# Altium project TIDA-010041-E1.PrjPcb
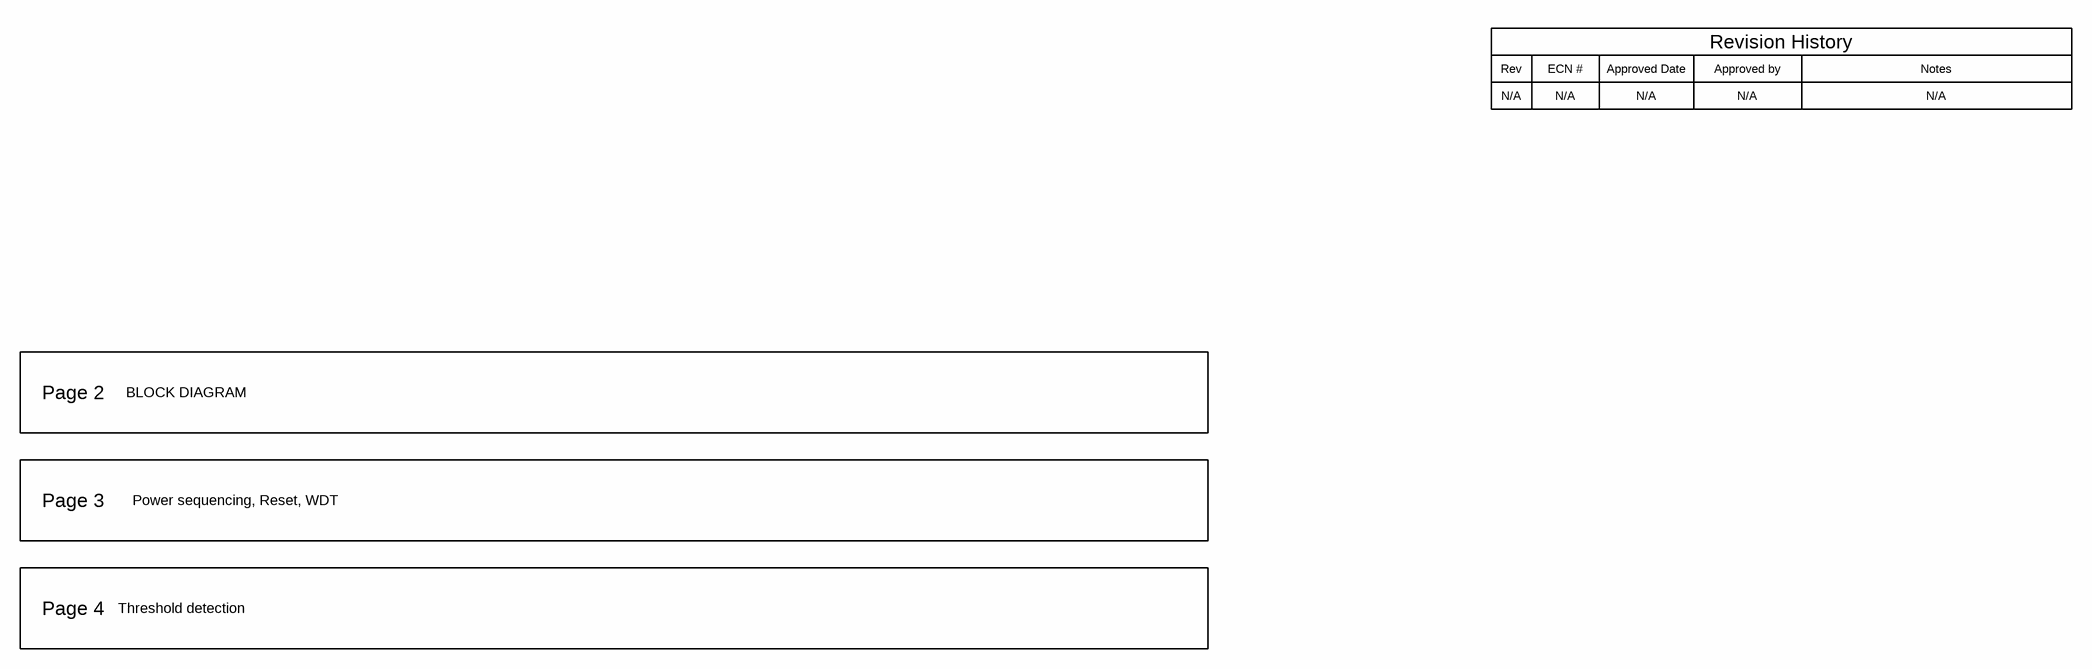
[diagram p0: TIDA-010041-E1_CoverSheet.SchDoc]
CopyrightYear: 2018; PCB_Layout: Avinash N; PCB_Rev: E1; PRJ_Customer: Public Release; PRJ_Engineer: Harsh Misra; PRJ_Number: TIDA-010041; PRJ_Title: TIDA-010041; SCH_Rev: E1; TechSupport: http://www.ti.com/support; TID: 010041
5 sheets, 147 parts. Net scope: flat (ports and power ports of the same name join across sheets).
Board file: TIDA-010041-E1.PcbDoc
Sheets:
  TIDA-010041-E1_CoverSheet.SchDoc
  TIDA-010041-E1_Block Diagram.SchDoc
  TIDA-010041-E1_Power sequencing, Reset, WDT.SchDoc
  TIDA-010041-E1_Threshold detection.SchDoc
  TIDA-010041-E1_EVM_Hardware.SchDoc

## Sheet TIDA-010041-E1_CoverSheet.SchDoc
size 431 x 279 mm; Date: Not shown in title block; ApprovedBy: Not shown in title block; CheckedBy: Not shown in title block; Author: Not shown in title block; CompanyName: Not shown in title block; Engineer: Not shown in title block; Organization: Not shown in title block; Address1: Not shown in title block; Address2: Not shown in title block; Address3: Not shown in title block; Address4: Not shown in title block; DocumentNumber: 1; Revision: Use project parameter SCH_Rev; SheetNumber: 1; SheetTotal: 5; PageSetup: Record=PageOptions¦CenterHorizontal=True¦CenterVertical=True¦PrintScale=1.00¦XCorrection=1.00¦YCorrection=1.00¦PrintKind=0¦BorderSize=5000000¦LeftOffset=0¦BottomOffset=0¦Orientation=2¦PaperLength=1000¦PaperWidth=1000¦Scale=100¦PaperSource=15¦PrintQuality=600¦MediaType=1¦DitherType=10¦PaperKind=Letter¦PrintScaleMode=1

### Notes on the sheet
- Rev
- N/A
- ECN #
- Approved Date
- Approved by
- Revision History
- Notes
- Page 2
- BLOCK DIAGRAM
- Page 3
- Power sequencing, Reset, WDT
- Page 4
- Threshold detection

## Sheet TIDA-010041-E1_Block Diagram.SchDoc
size 431 x 279 mm; Date: Not shown in title block; ApprovedBy: Not shown in title block; CheckedBy: Not shown in title block; Author: Not shown in title block; CompanyName: Not shown in title block; Engineer: Not shown in title block; Organization: Not shown in title block; Address1: Not shown in title block; Address2: Not shown in title block; Address3: Not shown in title block; Address4: Not shown in title block; DocumentNumber: 1; Revision: Use project parameter SCH_Rev; SheetNumber: 2; SheetTotal: 5; PageSetup: Record=PageOptions¦CenterHorizontal=True¦CenterVertical=True¦PrintScale=1.00¦XCorrection=1.00¦YCorrection=1.00¦PrintKind=0¦BorderSize=5000000¦LeftOffset=0¦BottomOffset=0¦Orientation=2¦PaperLength=1000¦PaperWidth=1000¦Scale=100¦PaperSource=15¦PrintQuality=600¦MediaType=1¦DitherType=10¦PaperKind=Letter¦PrintScaleMode=1
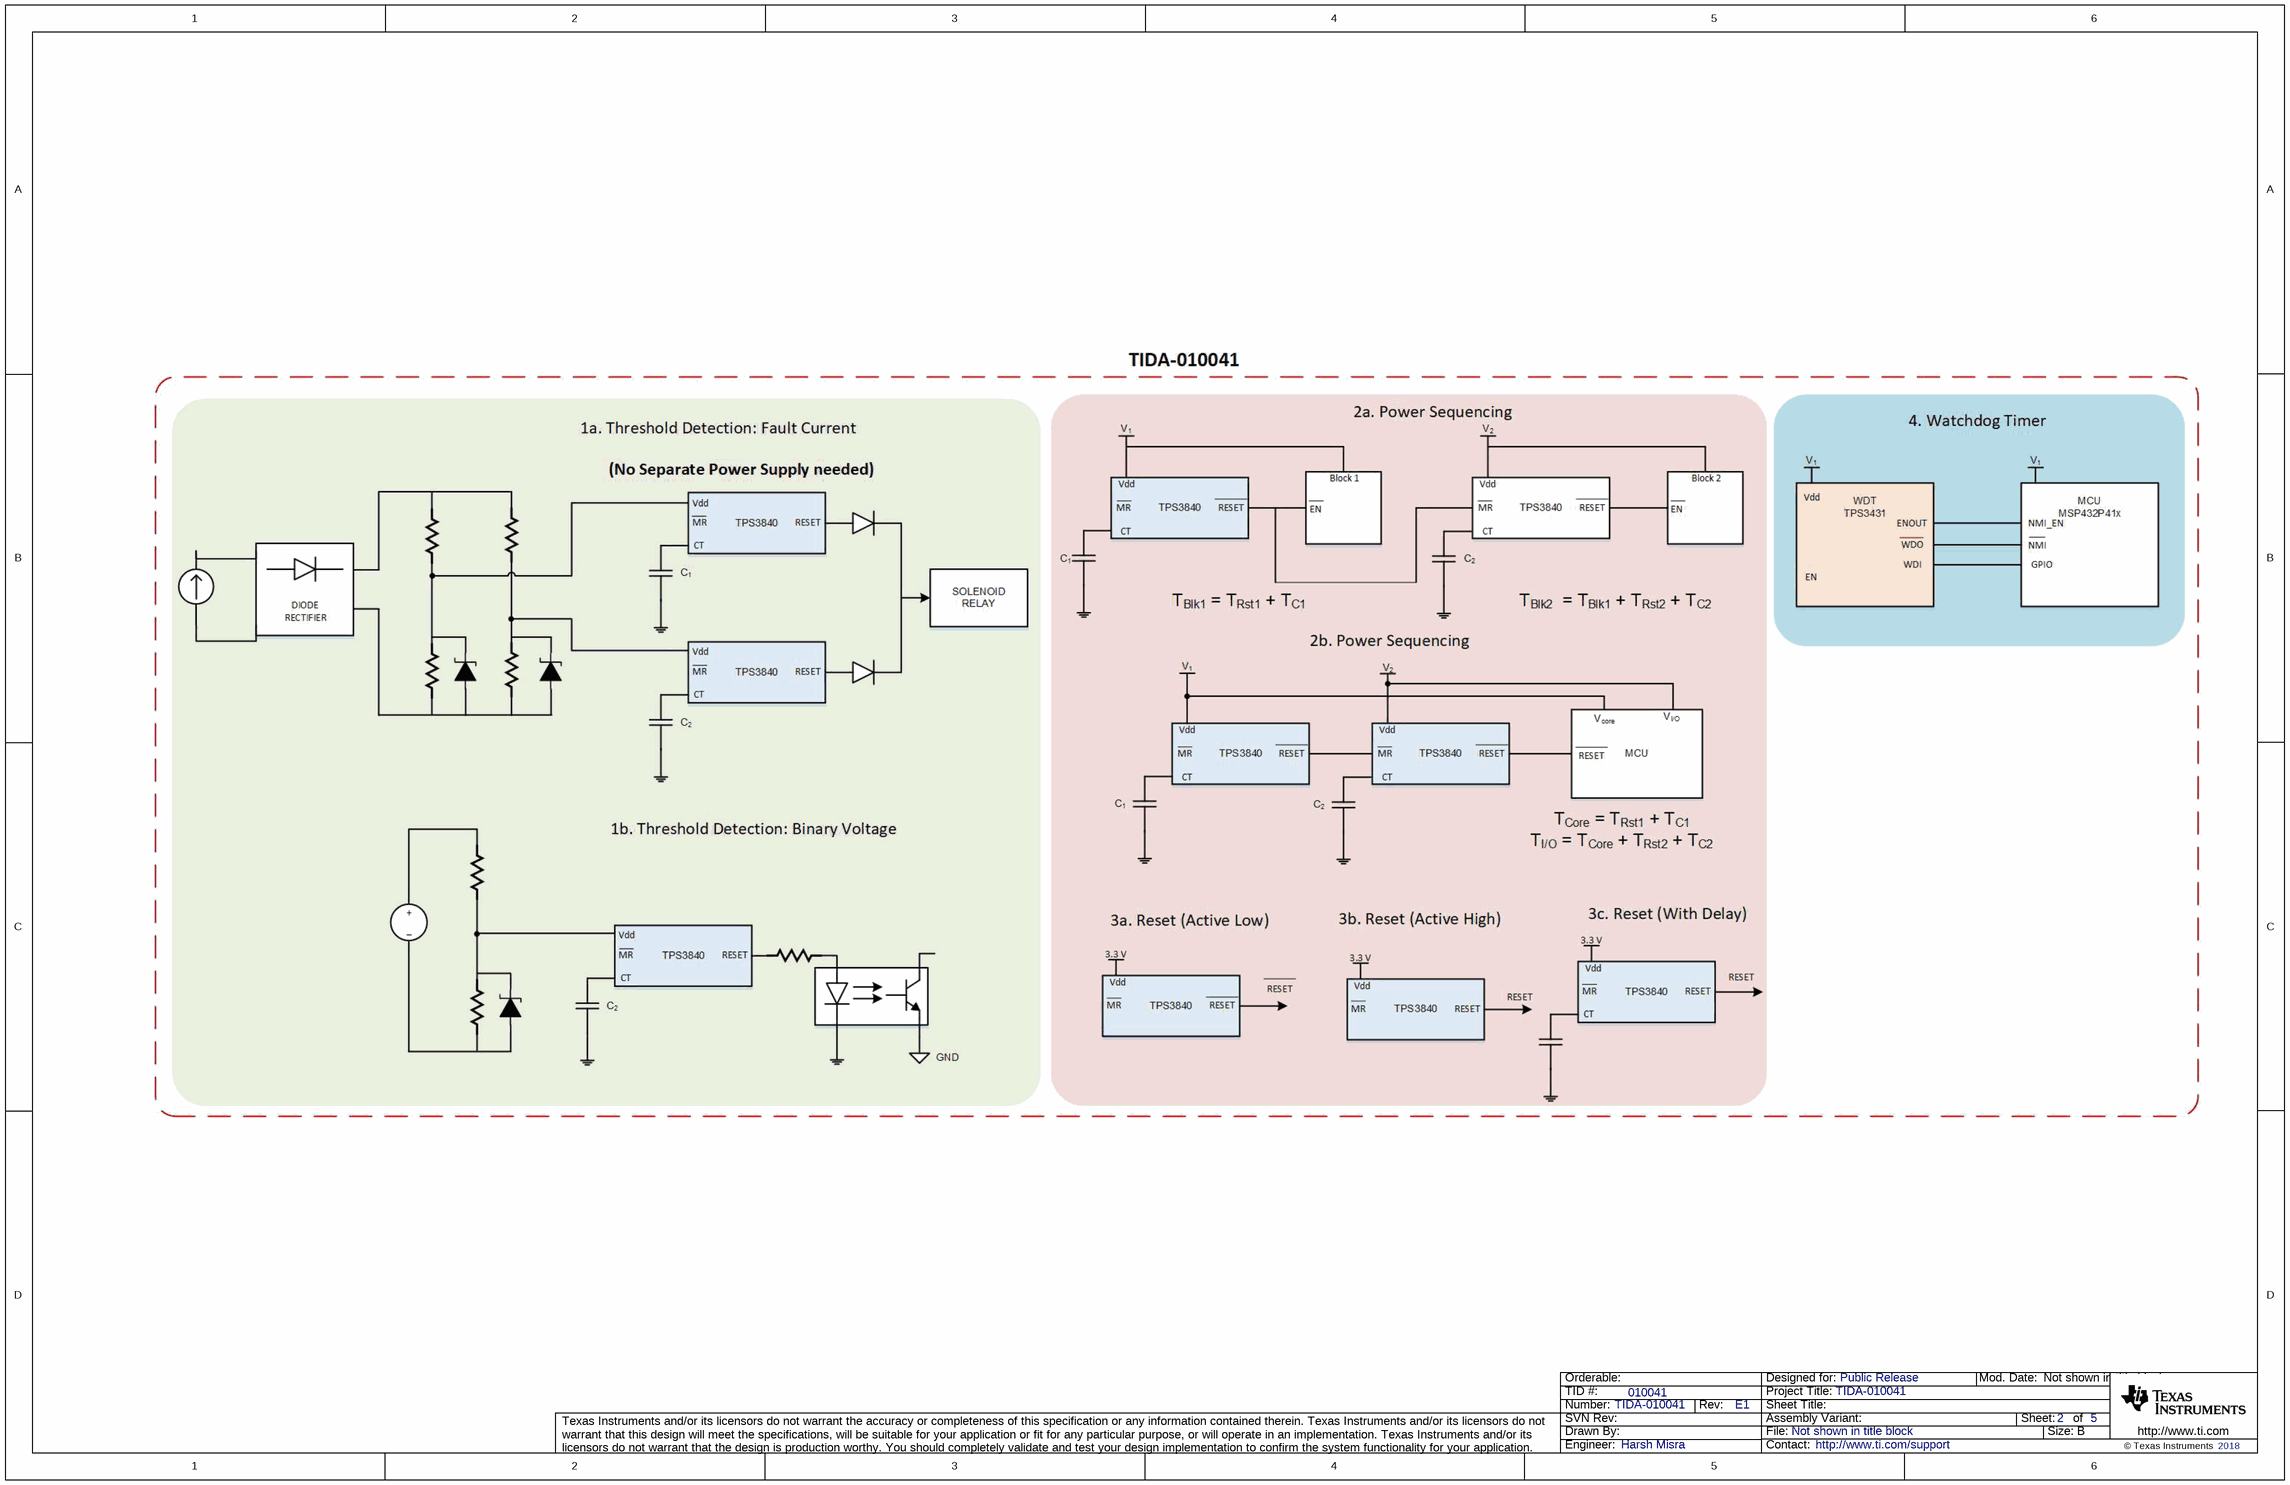
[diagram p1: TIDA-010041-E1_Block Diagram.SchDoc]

## Sheet TIDA-010041-E1_Power sequencing, Reset, WDT.SchDoc
size 431 x 279 mm; Date: Not shown in title block; ApprovedBy: Not shown in title block; CheckedBy: Not shown in title block; Author: Not shown in title block; CompanyName: Not shown in title block; Engineer: Not shown in title block; Organization: Not shown in title block; Address1: Not shown in title block; Address2: Not shown in title block; Address3: Not shown in title block; Address4: Not shown in title block; DocumentNumber: 1; Revision: Use project parameter SCH_Rev; SheetNumber: 3; SheetTotal: 5; PageSetup: Record=PageOptions¦CenterHorizontal=True¦CenterVertical=True¦PrintScale=1.00¦XCorrection=1.00¦YCorrection=1.00¦PrintKind=0¦BorderSize=5000000¦LeftOffset=0¦BottomOffset=0¦Orientation=2¦PaperLength=1000¦PaperWidth=1000¦Scale=100¦PaperSource=15¦PrintQuality=600¦MediaType=1¦DitherType=10¦PaperKind=Letter¦PrintScaleMode=1
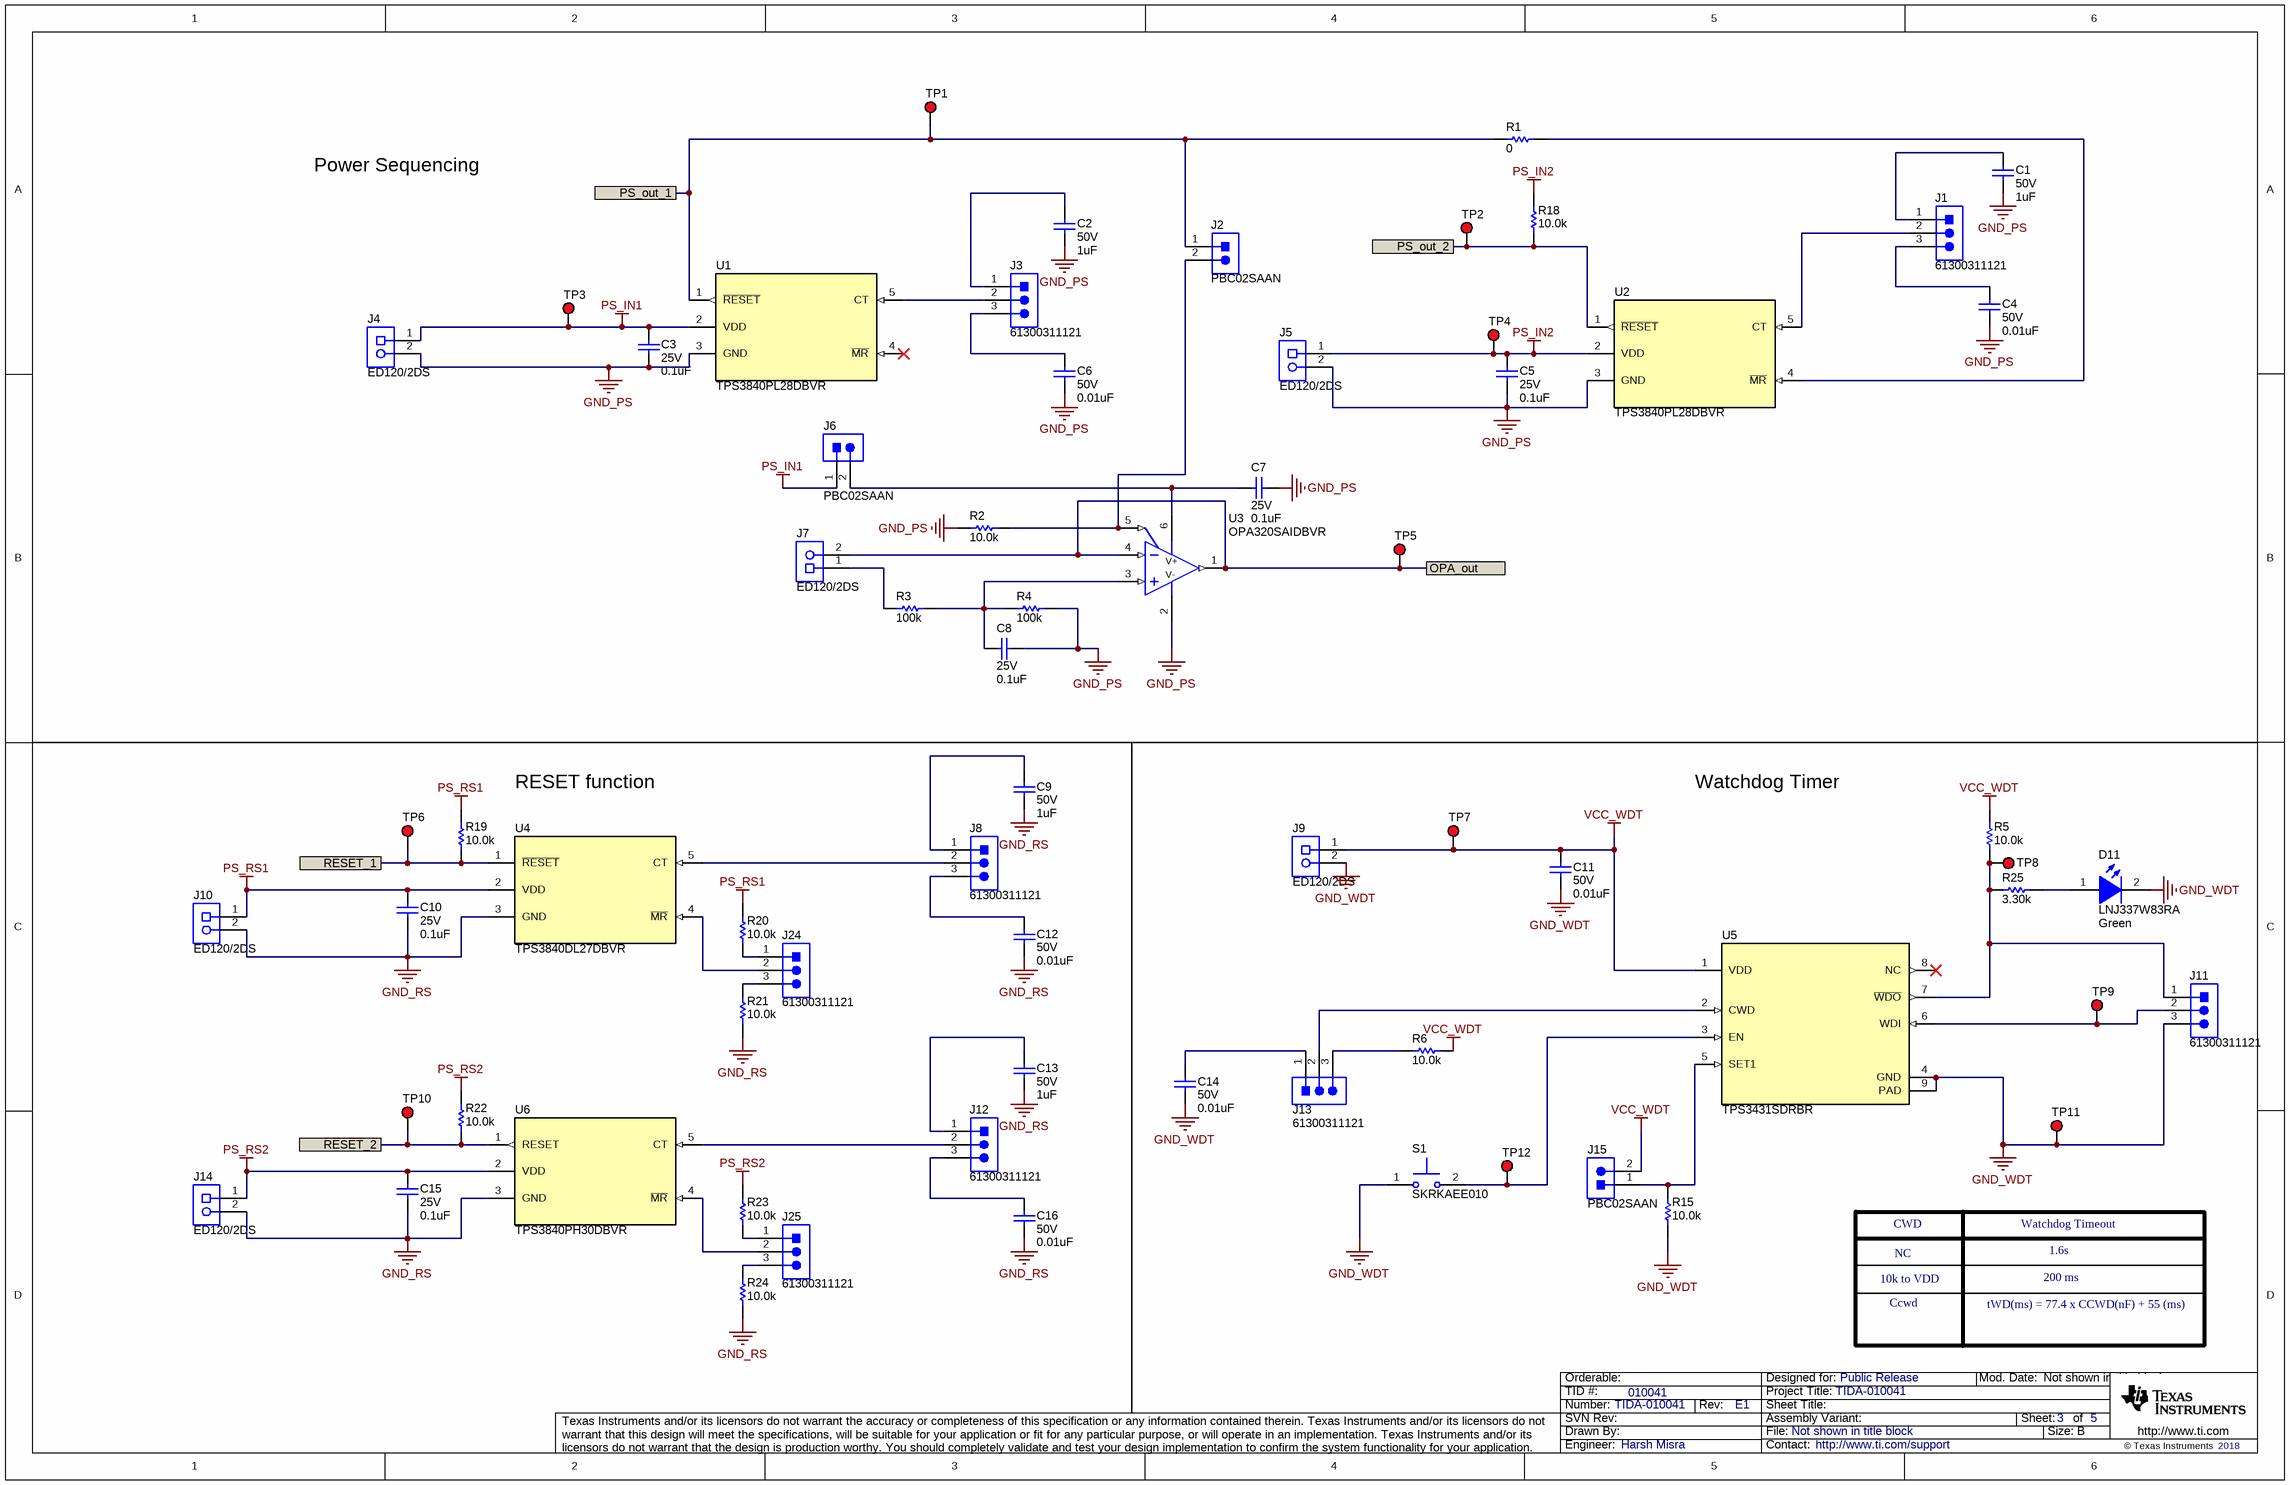
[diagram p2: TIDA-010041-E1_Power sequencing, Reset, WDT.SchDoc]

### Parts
C1  VDC_V: 50V  ValueDisplayed: 1uF  [1210_180]  (hidden comment: C3225X7R1H105K160AA)
C2  VDC_V: 50V  ValueDisplayed: 1uF  [1210_180]  (hidden comment: C3225X7R1H105K160AA)
C3  VDC_V: 25V  ValueDisplayed: 0.1uF  [0805_HV]  (hidden comment: 08053C104JAT2A)
C4  VDC_V: 50V  ValueDisplayed: 0.01uF  [0805_HV]  (hidden comment: 08055C103JAT2A)
C5  VDC_V: 25V  ValueDisplayed: 0.1uF  [0805_HV]  (hidden comment: 08053C104JAT2A)
C6  VDC_V: 50V  ValueDisplayed: 0.01uF  [0805_HV]  (hidden comment: 08055C103JAT2A)
C7  VDC_V: 25V  ValueDisplayed: 0.1uF  [0805_HV]  (hidden comment: 08053C104JAT2A)
C8  VDC_V: 25V  ValueDisplayed: 0.1uF  [0805_HV]  (hidden comment: 08053C104JAT2A)
C9  VDC_V: 50V  ValueDisplayed: 1uF  [1210_180]  (hidden comment: C3225X7R1H105K160AA)
C10  VDC_V: 25V  ValueDisplayed: 0.1uF  [0805_HV]  (hidden comment: 08053C104JAT2A)
C11  VDC_V: 50V  ValueDisplayed: 0.01uF  [0805_HV]  (hidden comment: 08055C103JAT2A)
C12  VDC_V: 50V  ValueDisplayed: 0.01uF  [0805_HV]  (hidden comment: 08055C103JAT2A)
C13  VDC_V: 50V  ValueDisplayed: 1uF  [1210_180]  (hidden comment: C3225X7R1H105K160AA)
C14  VDC_V: 50V  ValueDisplayed: 0.01uF  [0805_HV]  (hidden comment: 08055C103JAT2A)
C15  VDC_V: 25V  ValueDisplayed: 0.1uF  [0805_HV]  (hidden comment: 08053C104JAT2A)
C16  VDC_V: 50V  ValueDisplayed: 0.01uF  [0805_HV]  (hidden comment: 08055C103JAT2A)
D11  LNJ337W83RA  value Green  [LNJx37x8_Green]
J1  61300311121  [WURTH_61300311121]
J2  PBC02SAAN  [Sullins_PBC02SAAN]
J3  61300311121  [WURTH_61300311121]
J4  ED120/2DS  [On-Shore_ED120_2DS]
J5  ED120/2DS  [On-Shore_ED120_2DS]
J6  PBC02SAAN  [Sullins_PBC02SAAN]
J7  ED120/2DS  [On-Shore_ED120_2DS]
J8  61300311121  [WURTH_61300311121]
J9  ED120/2DS  [On-Shore_ED120_2DS]
J10  ED120/2DS  [On-Shore_ED120_2DS]
J11  61300311121  [WURTH_61300311121]
J12  61300311121  [WURTH_61300311121]
J13  61300311121  [WURTH_61300311121]
J14  ED120/2DS  [On-Shore_ED120_2DS]
J15  PBC02SAAN  [Sullins_PBC02SAAN]
J24  61300311121  [WURTH_61300311121]
J25  61300311121  [WURTH_61300311121]
R1  ValueDisplayed: 0  [5106]  (hidden comment: 5106)
R2  ValueDisplayed: 10.0k  [0805_HV]  (hidden comment: MCU08050C1002FP500)
R3  ValueDisplayed: 100k  [0805_HV]  (hidden comment: MCU08050C1003FP500)
R4  ValueDisplayed: 100k  [0805_HV]  (hidden comment: MCU08050C1003FP500)
R5  ValueDisplayed: 10.0k  [0805_HV]  (hidden comment: PLTT0805Z1002QGT5)
R6  ValueDisplayed: 10.0k  [0805_HV]  (hidden comment: PLTT0805Z1002QGT5)
R15  ValueDisplayed: 10.0k  [0805_HV]  (hidden comment: PLTT0805Z1002QGT5)
R18  ValueDisplayed: 10.0k  [0402]  (hidden comment: ERJ-2RKF1002X)
R19  ValueDisplayed: 10.0k  [0402]  (hidden comment: ERJ-2RKF1002X)
R20  ValueDisplayed: 10.0k  [0402]  (hidden comment: ERJ-2RKF1002X)
R21  ValueDisplayed: 10.0k  [0402]  (hidden comment: ERJ-2RKF1002X)
R22  ValueDisplayed: 10.0k  [0402]  (hidden comment: ERJ-2RKF1002X)
R23  ValueDisplayed: 10.0k  [0402]  (hidden comment: ERJ-2RKF1002X)
R24  ValueDisplayed: 10.0k  [0402]  (hidden comment: ERJ-2RKF1002X)
R25  ValueDisplayed: 3.30k  [0603]  (hidden comment: RG1608P-332-B-T5)
S1  SKRKAEE010  [SW_SKRKAEE010]
TP1  (no value)  [Keystone5000]
TP2  (no value)  [Keystone5000]
TP3  (no value)  [Keystone5000]
TP4  (no value)  [Keystone5000]
TP5  (no value)  [Keystone5000]
TP6  (no value)  [Keystone5000]
TP7  (no value)  [Keystone5000]
TP8  (no value)  [Keystone5000]
TP9  (no value)  [Keystone5000]
TP10  (no value)  [Keystone5000]
TP11  (no value)  [Keystone5000]
TP12  (no value)  [Keystone5000]
U1  TPS3840PL28DBVR  [DBV0005A_N]
U2  TPS3840PL28DBVR  [DBV0005A_N]
U3  OPA320SAIDBVR  [DBV0006A_L]
U4  TPS3840DL27DBVR  [DBV0005A_N]
U5  TPS3431SDRBR  [DRB0008A]
U6  TPS3840PH30DBVR  [DBV0005A_N]

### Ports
OPA_out, PS_out_1, PS_out_2, RESET_1, RESET_2

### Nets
GND_PS: C1.2 C2.2 C3.2 C4.2 C5.2 C6.2 C7.1 C8.2 J4.2 J5.2 R2.1 R4.1 U1.3(GND) U2.3(GND) U3.2(V-)
GND_RS: C9.2 C10.1 C12.2 C13.2 C15.1 C16.2 J10.2 J14.2 R21.1 R24.1 U4.3(GND) U6.3(GND)
GND_WDT: C11.2 C14.2 D11.2(K) J9.2 J11.3 R15.2 S1.1 TP11.1 U5.4(GND) U5.9(PAD)
PS_IN1: C3.1 J4.1 J6.1 TP3.1 U1.2(VDD)
PS_IN2: C5.1 J5.1 R18.2 TP4.1 U2.2(VDD)
PS_RS1: C10.2 J10.1 R19.2 R20.2 U4.2(VDD)
PS_RS2: C15.2 J14.1 R22.2 R23.2 U6.2(VDD)
VCC_WDT: C11.1 J9.1 J15.2 R5.1 R6.1 TP7.1 U5.1(VDD)
OPA_out: J7.2 TP5.1 U3.1(OUT) U3.4(IN-) ; port OPA_out
PS_out_1: J2.1 R1.1 TP1.1 U1.1(~{RESET}) ; port PS_out_1
PS_out_2: R18.1 TP2.1 U2.1(~{RESET}) ; port PS_out_2
RESET_1: R19.1 TP6.1 U4.1(~{RESET}) ; port RESET_1
RESET_2: R22.1 TP10.1 U6.1(RESET) ; port RESET_2
NetC1_1: C1.1 J1.1
NetC2_1: C2.1 J3.1
NetC4_1: C4.1 J1.3
NetC6_1: C6.1 J3.3
NetC7_2: C7.2 J6.2 U3.6(V+)
NetC8_1: C8.1 R3.1 R4.2 U3.3(IN+)
NetC9_1: C9.1 J8.1
NetC12_1: C12.1 J8.3
NetC13_1: C13.1 J12.1
NetC14_1: C14.1 J13.1
NetC16_1: C16.1 J12.3
NetD11_1: D11.1(A) R25.2
NetJ1_2: J1.2 U2.5(CT)
NetJ2_2: J2.2 R2.2 U3.5(SD)
NetJ3_2: J3.2 U1.5(CT)
NetJ7_1: J7.1 R3.2
NetJ8_2: J8.2 U4.5(CT)
NetJ11_1: J11.1 R5.2 R25.1 TP8.1 U5.7(~{WDO})
NetJ11_2: J11.2 TP9.1 U5.6(WDI)
NetJ12_2: J12.2 U6.5(CT)
NetJ13_2: J13.2 U5.2(CWD)
NetJ13_3: J13.3 R6.2
NetJ15_1: J15.1 R15.1 U5.5(SET1)
NetJ24_1: J24.1 R20.1
NetJ24_2: J24.2 U4.4(~{MR})
NetJ24_3: J24.3 R21.2
NetJ25_1: J25.1 R23.1
NetJ25_2: J25.2 U6.4(~{MR})
NetJ25_3: J25.3 R24.2
NetR1_2: R1.2 U2.4(~{MR})
NetS1_2: S1.2 TP12.1 U5.3(EN)

Not connected (* = marked no-connect by the designer): U1 4(~{MR})*; U5 8(NC)*

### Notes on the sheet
- Power Sequencing
- RESET function
- Watchdog Timer
- CWD
- Watchdog Timeout
- 10k to VDD
- Ccwd
- NC
- 200 ms
- 1.6s
- tWD(ms) = 77.4 x CCWD(nF) + 55 (ms)

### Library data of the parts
C1 C2 C9 C13 = CMP-0009119-1: CAP, CERM, 1 uF, 50 V, +/- 10%, X7R, 1210; Manufacturer: TDK; TaMin_C: -55°C; ESR_ohm: 7.168m; Polarized: N; SizeAreaWB_mm2: 14.7; Value1: 0.007168 ohm; U/M: EA; Value: 1uF; TaMax_C: 125°C; SizeZ_mm: 1.8; SizeX_mm: 3.2; SizeY_mm: 2.5; SizeArea_mm2: 8; Cap_F: 1µF; IRMS_A: 2.75026A; AEC Category: Q200
C3 C5 C7 C8 C10 C15 = CMP-0007565-2: CAP, CERM, 0.1 uF, 25 V, +/- 5%, X7R, 0805; Manufacturer: AVX; TaMin_C: -55°C; Polarized: N; SizeAreaWB_mm2: 6.75; Value1: Unknown; U/M: EA; Value: 0.1uF; TaMax_C: 125°C; SizeZ_mm: 1.45; SizeX_mm: 2; SizeY_mm: 1.25; Cap_Case: 0805; SizeArea_mm2: 2.5; Cap_F: 100nF; AEC Category: Q200
C4 C6 C11 C12 C14 C16 = CMP-0007629-2: CAP, CERM, 0.01 uF, 50 V, +/- 5%, X7R, 0805; Manufacturer: AVX; TaMin_C: -55°C; ESR_ohm: 0.078; Polarized: N; SizeAreaWB_mm2: 6.75; Value1: 0.078 ohm; U/M: EA; Value: 0.01uF; TaMax_C: 125°C; SizeZ_mm: 1.45; SizeX_mm: 2; SizeY_mm: 1.25; Cap_Case: 0805; SizeArea_mm2: 2.5; Cap_F: 10nF; AEC Category: Q200
D11 = CMP-0002976-2: LED, Green, SMD; Manufacturer: Panasonic; Io_A: 5mA; Vr_V: 4V; Tjmax_C: 85°C; Value1: W; U/M: EA; Ir_A: 10µA; Vf_V: 1.95V
J1 J3 J8 J11-J13 J24 J25 = CMP-0054796-1: Header, 2.54 mm, 3x1, Gold, TH; Manufacturer: Wurth Elektronik; CNHeader: TRUE; Green_Lifecycle: Active; Green_REACh: Passed; CT: FALSE
J2 J6 J15 = CMP-0054566-1: Header, 100mil, 2x1, Gold, TH; Manufacturer: Sullins Connector Solutions; CNHeader: TRUE; Current_A: 3A; Green_Lifecycle: Active; Shrouded: N; Gender: Male; Green_REACh: Passed; Voltage_V: 1.8kV; Row_Count: 1; Pitch_mm: 2.54; CT: FALSE; Cert_UL: Y
J4 J5 J7 J9 J10 J14 = CMP-0074910-1: Terminal Block, 5.08 mm, 2x1, Brass, TH; Manufacturer: On-Shore Technology; Cert_VDE: Y; CNHeader: False; Current_A: 15A; Green_Lifecycle: Not Set; Shrouded: N; Gender: Female; Green_REACh: Incomplete; Voltage_V: 300V; Row_Count: 1; Pitch_mm: 5.08; CT: True
R1 = CMP-0020833-2: RES, 0, 1%, 0.5 W, 0805; Manufacturer: Keystone; Power_W: 500mW; TempCo: ppm/C; U/M: EA; Value: 0; SizeX_mm: 2; SizeY_mm: 1.25; SizeZ_mm: 0.84; Value2: 0.5W; SizeArea_mm2: 2.5; AEC Qualified: N; AEC Category: Q200
R2 = CMP-0021857-2: RES, 10.0 k, 1%, 0.2 W, 0805; Manufacturer: Vishay/Beyschlag; Power_W: 200mW; TempCo: 50 ppm/C; Value_Code: 10k0; U/M: EA; Value: 10.0k; EIA_Code: E96; Res_ohm: 10k; SizeX_mm: 2; SizeY_mm: 1.25; SizeZ_mm: 1.45; Value2: 0.2W; SizeArea_mm2: 2.5; AEC Qualified: N; VDC_V: 150V; AEC Category: Q200
R3 R4 = CMP-0021858-2: RES, 100 k, 1%, 0.2 W, 0805; Manufacturer: Vishay/Beyschlag; Power_W: 200mW; TempCo: 50 ppm/C; U/M: EA; Value: 100k; EIA_Code: E96; SizeX_mm: 2; SizeY_mm: 1.25; SizeZ_mm: 1.45; Value2: 0.2W; SizeArea_mm2: 2.5; AEC Qualified: N; VDC_V: 150V; AEC Category: Q200
R5 R6 R15 = CMP-0018847-1: RES, 10.0 k, 0.02%, 0.25 W, 0805; Manufacturer: Vishay-Dale; Power_W: 250mW; TempCo: 5 ppm/C; Value_Code: 10k0; U/M: EA; Value: 10.0k; Res_ohm: 10k; SizeX_mm: 2; SizeY_mm: 1.25; SizeZ_mm: 1.45; Value2: 0.25W; SizeArea_mm2: 2.5; AEC Category: Q200
R18-R24 = ERJ-2RKF1002X: RES, 10.0 k, 1%, 0.1 W, 0402; Manufacturer: Panasonic; CompType: Resistor; Value: 10.0k; Res_ohm: 10000; Value_Code: 10k0; Tolerance_%: 1; Power_W: 0.1; Value2: 0.1W; VDC_V: 50; TempCo: 100 ppm/C; SizeArea_mm2: 0.5; SizeZ_mm: 0.6; EIA_Code: E96; U/M: EA; AEC Category: Q200; Green_Lifecycle: Active; Green_REACh: Passed
R25 = RG1608P-332-B-T5: RES, 3.30 k, 0.1%, 0.1 W, 0603; Manufacturer: Susumu Co Ltd; CompType: Resistor; Value: 3.30k; Res_ohm: 3300; Value_Code: 3k30; Tolerance_%: 0.1; Value2: 0.1W; VDC_V: 75; TempCo: 25 ppm/C; SizeArea_mm2: 1.28; SizeX_mm: 1.6; SizeY_mm: 0.8; SizeZ_mm: 1; U/M: EA; AEC Category: Q200; Green_Lifecycle: Active; Green_REACh: Passed
S1 = CMP-0002113-2: Switch, Push Button, SMD; Manufacturer: Alps; CurrentRating_mA: 50A; SwitchFunction: Off-Mom; Circuit: SPST-NO; VDC_V: 12V; PositionCount: 1
TP1-TP12 = CMP-0055137-1: Test Point, Miniature, Red, TH; Manufacturer: Keystone; CNHeader: FALSE; Green_Lifecycle: Active; Green_REACh: Passed; ContactFinish: Silver; CT: TRUE
U1 U2 = CMP-0079923-1: Nano Power, Wide VIN Voltage Detector with Programmable Delay, DBV0005A (SOT-23-5); Alternate Manufacturer: Texas Instruments; SizeAreaWB_mm2: 14.82; SizeZ_mm: 1.45; SizeX_mm: 2.8; SizeY_mm: 2.9; SizeArea_mm2: 8.12; CompType: IC; AEC Qualified: N; AEC Category: Q200
U3 = CMP-0075795-1: Precision, 20MHz, 0.9pA Ib, RRIO, CMOS Operational Amplifier, DBV0006A (SOT-23-6); Manufacturer: Texas Instruments; Alternate PartNumber: OPA320SAIDBVT; SizeAreaWB_mm2: 14.82; SizeArea_mm2: 8.12; SizeZ_mm: 1.45; SizeY_mm: 2.9; U/M: EA; CompType: IC; SizeX_mm: 2.8
U4 = CMP-0079925-1: Nano Power, Wide VIN Voltage Detector with Programmable Delay, DBV0005A (SOT-23-5); Alternate Manufacturer: Texas Instruments; SizeAreaWB_mm2: 14.82; SizeZ_mm: 1.45; SizeX_mm: 2.8; SizeY_mm: 2.9; SizeArea_mm2: 8.12; CompType: IC; AEC Qualified: N; AEC Category: Q200
U5 = CMP-0081798-1: Stand Alone Watchdog with programmable timeout period, DRB0008A (VSON-8); Alternate Manufacturer: Texas Instruments; SizeAreaWB_mm2: 16; Rating: Catalog; SizeZ_mm: 1; SizeX_mm: 3; SizeArea_mm2: 9; CompType: IC; AEC Qualified: N; AEC Category: Q200
U6 = CMP-0079924-1: Nano Power, Wide VIN Voltage Detector with Programmable Delay, DBV0005A (SOT-23-5); Alternate Manufacturer: Texas Instruments; SizeAreaWB_mm2: 14.82; SizeZ_mm: 1.45; SizeX_mm: 2.8; SizeY_mm: 2.9; SizeArea_mm2: 8.12; CompType: IC; AEC Qualified: N; AEC Category: Q200

## Sheet TIDA-010041-E1_Threshold detection.SchDoc
size 431 x 279 mm; Date: Not shown in title block; ApprovedBy: Not shown in title block; CheckedBy: Not shown in title block; Author: Not shown in title block; CompanyName: Not shown in title block; DrawnBy: Harsh Misra; Engineer: Harsh Misra; Organization: Industrial; Address1: Not shown in title block; Address2: Not shown in title block; Address3: Not shown in title block; Address4: Not shown in title block; DocumentNumber: 1; Revision: Use project parameter SCH_Rev; SheetNumber: 4; SheetTotal: 5; PageSetup: Record=PageOptions¦CenterHorizontal=True¦CenterVertical=True¦PrintScale=1.00¦XCorrection=1.00¦YCorrection=1.00¦PrintKind=0¦BorderSize=5000000¦LeftOffset=0¦BottomOffset=0¦Orientation=2¦PaperLength=1000¦PaperWidth=1000¦Scale=100¦PaperSource=15¦PrintQuality=600¦MediaType=1¦DitherType=10¦PaperKind=Letter¦PrintScaleMode=1
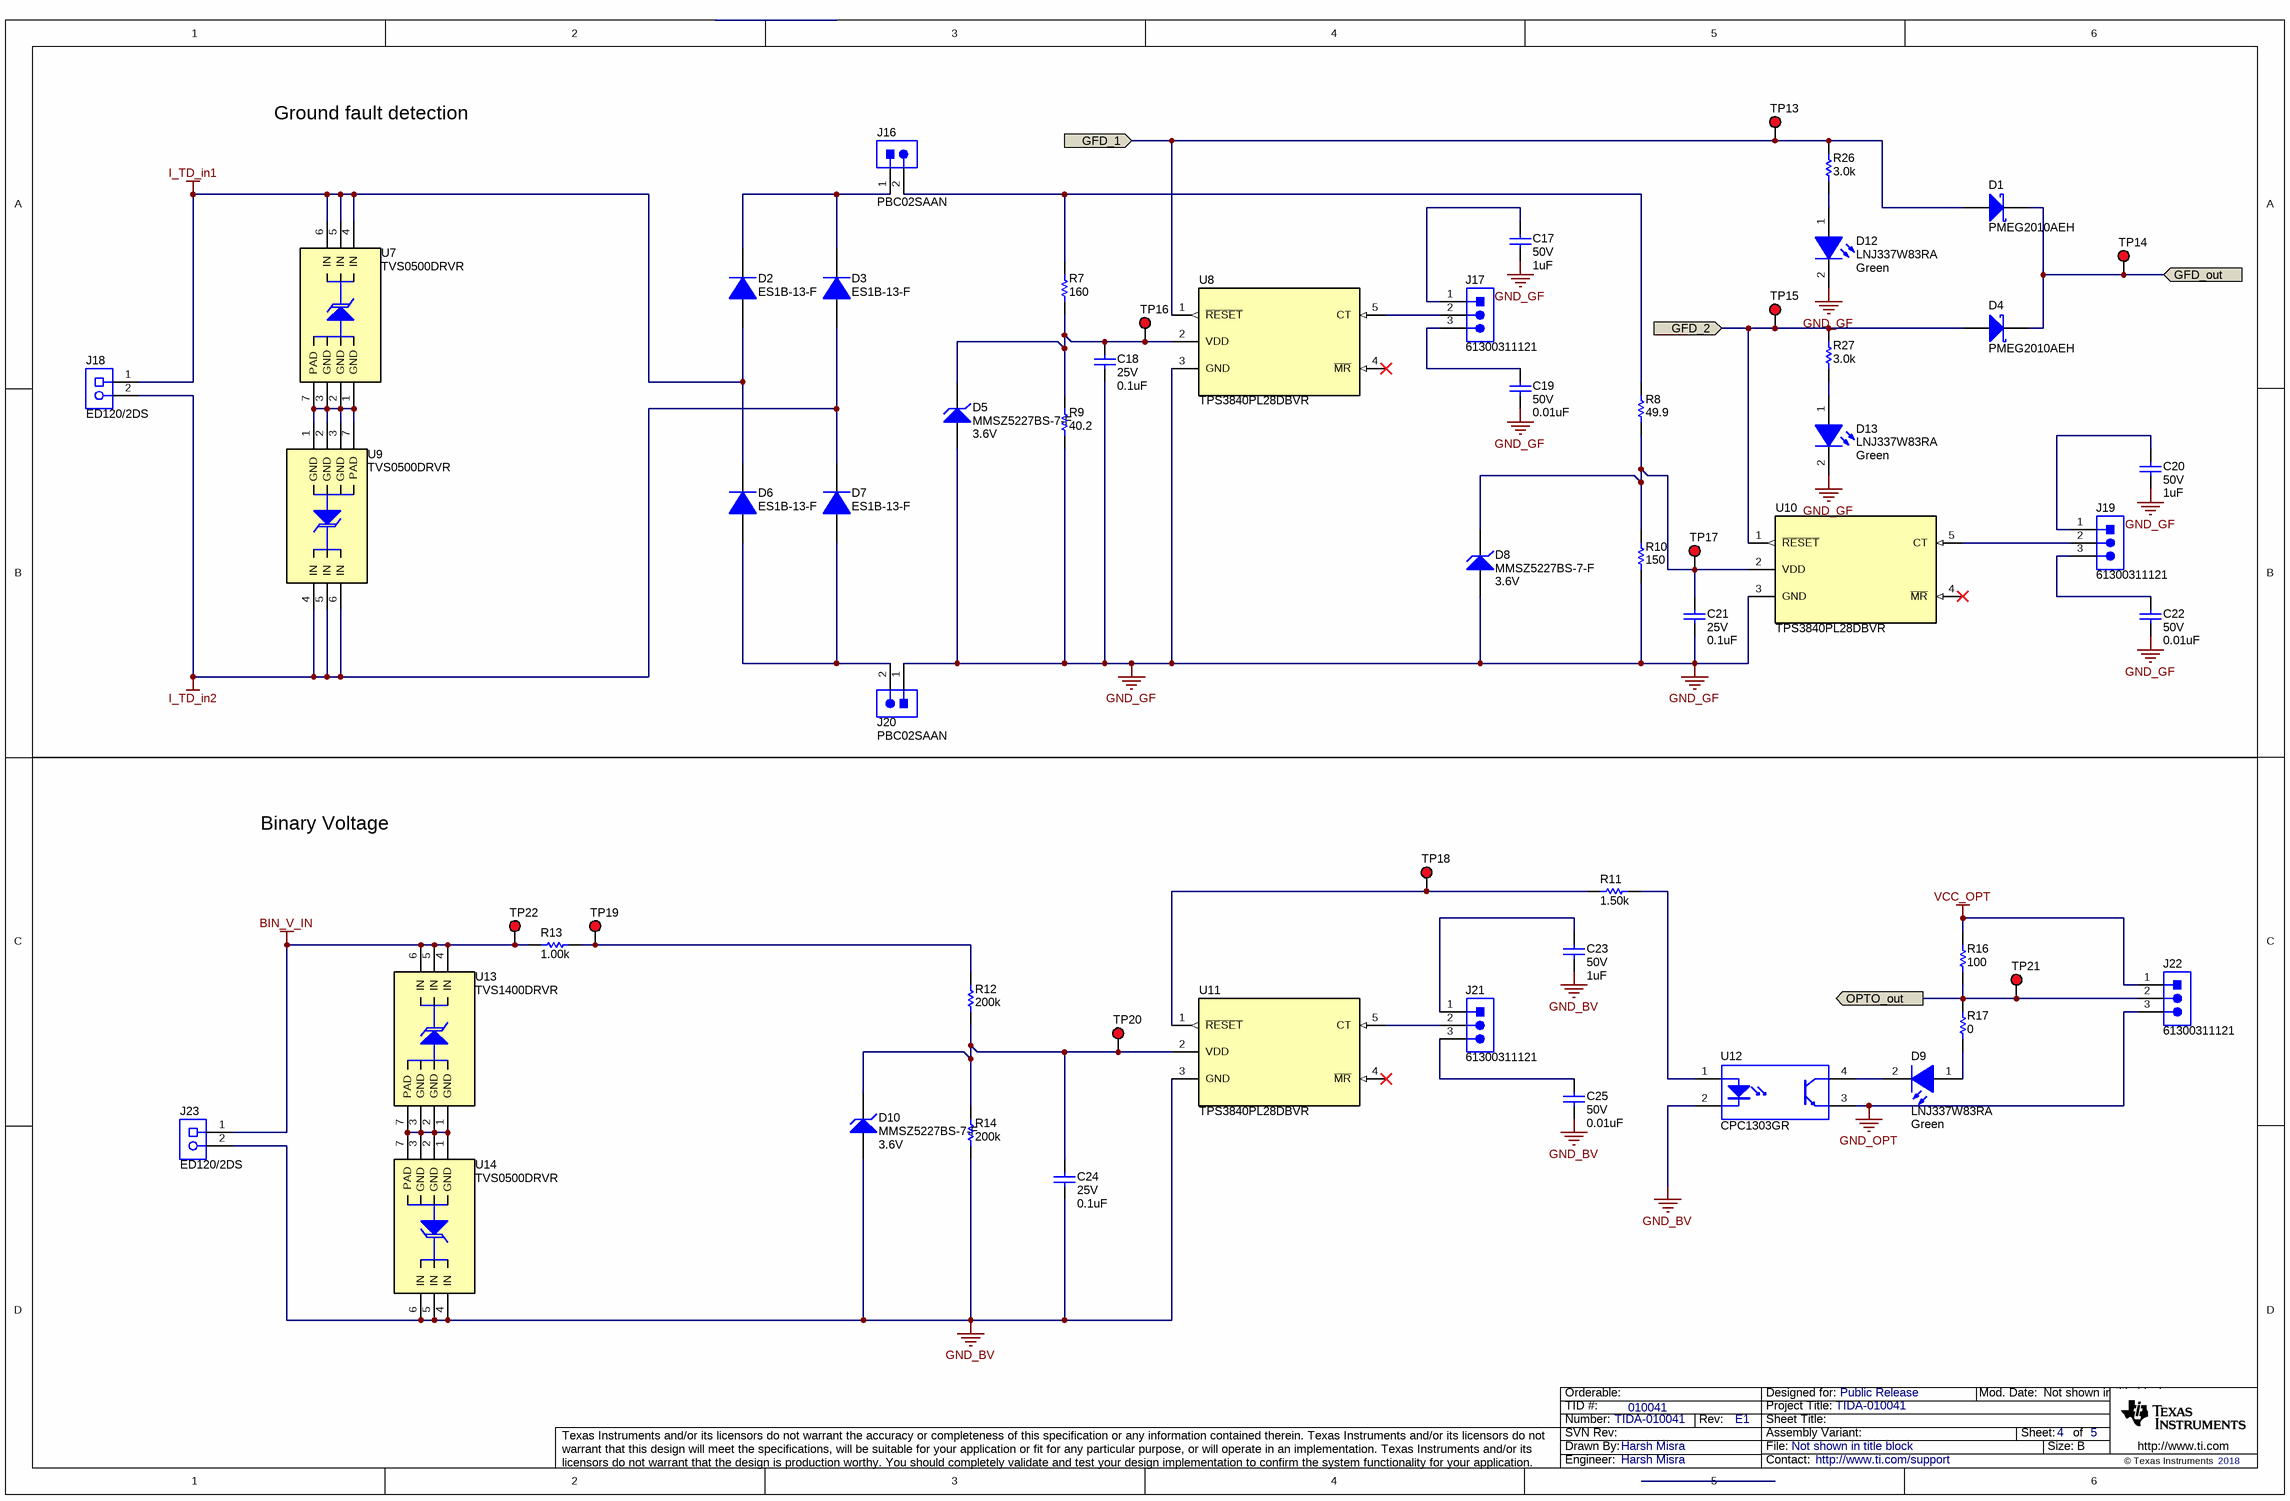
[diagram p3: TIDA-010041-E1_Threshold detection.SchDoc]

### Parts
C17  VDC_V: 50V  ValueDisplayed: 1uF  [1210_180]  (hidden comment: C3225X7R1H105K160AA)
C18  VDC_V: 25V  ValueDisplayed: 0.1uF  [0805_HV]  (hidden comment: 08053C104JAT2A)
C19  VDC_V: 50V  ValueDisplayed: 0.01uF  [0805_HV]  (hidden comment: 08055C103JAT2A)
C20  VDC_V: 50V  ValueDisplayed: 1uF  [1210_180]  (hidden comment: C3225X7R1H105K160AA)
C21  VDC_V: 25V  ValueDisplayed: 0.1uF  [0805_HV]  (hidden comment: 08053C104JAT2A)
C22  VDC_V: 50V  ValueDisplayed: 0.01uF  [0805_HV]  (hidden comment: 08055C103JAT2A)
C23  VDC_V: 50V  ValueDisplayed: 1uF  [1210_180]  (hidden comment: C3225X7R1H105K160AA)
C24  VDC_V: 25V  ValueDisplayed: 0.1uF  [0805_HV]  (hidden comment: 08053C104JAT2A)
C25  VDC_V: 50V  ValueDisplayed: 0.01uF  [0805_HV]  (hidden comment: 08055C103JAT2A)
D1  PMEG2010AEH  [SOD-123F]
D2  ES1B-13-F  [SMA]
D3  ES1B-13-F  [SMA]
D4  PMEG2010AEH  [SOD-123F]
D5  MMSZ5227BS-7-F  value 3.6V  [SOD-323]
D6  ES1B-13-F  [SMA]
D7  ES1B-13-F  [SMA]
D8  MMSZ5227BS-7-F  value 3.6V  [SOD-323]
D9  LNJ337W83RA  value Green  [LNJx37x8_Green]
D10  MMSZ5227BS-7-F  value 3.6V  [SOD-323]
D12  LNJ337W83RA  value Green  [LNJx37x8_Green]
D13  LNJ337W83RA  value Green  [LNJx37x8_Green]
J16  PBC02SAAN  [Sullins_PBC02SAAN]
J17  61300311121  [WURTH_61300311121]
J18  ED120/2DS  [On-Shore_ED120_2DS]
J19  61300311121  [WURTH_61300311121]
J20  PBC02SAAN  [Sullins_PBC02SAAN]
J21  61300311121  [WURTH_61300311121]
J22  61300311121  [WURTH_61300311121]
J23  ED120/2DS  [On-Shore_ED120_2DS]
R7  ValueDisplayed: 160  [0805_HV]  (hidden comment: RG2012P-161-B-T5)
R8  ValueDisplayed: 49.9  [0805_HV]  (hidden comment: ERJ-6ENF49R9V)
R9  ValueDisplayed: 40.2  [0805_HV]  (hidden comment: CRCW080540R2FKEA)
R10  ValueDisplayed: 150  [0805_HV]  (hidden comment: RG2012P-151-B-T5)
R11  ValueDisplayed: 1.50k  [0805_HV]  (hidden comment: RR1220P-152-D)
R12  ValueDisplayed: 200k  [0805_HV]  (hidden comment: ERJ-6GEYJ204V)
R13  ValueDisplayed: 1.00k  [0805_HV]  (hidden comment: RG2012P-102-B-T5)
R14  ValueDisplayed: 200k  [0805_HV]  (hidden comment: ERJ-6GEYJ204V)
R16  ValueDisplayed: 100  [0603]  (hidden comment: ERJ-3EKF1000V)
R17  ValueDisplayed: 0  [0603]  (hidden comment: ERJ-3GEY0R00V)
R26  ValueDisplayed: 3.0k  [0603]  (hidden comment: CRCW06033K00JNEA)
R27  ValueDisplayed: 3.0k  [0603]  (hidden comment: CRCW06033K00JNEA)
TP13  (no value)  [Keystone5000]
TP14  (no value)  [Keystone5000]
TP15  (no value)  [Keystone5000]
TP16  (no value)  [Keystone5000]
TP17  (no value)  [Keystone5000]
TP18  (no value)  [Keystone5000]
TP19  (no value)  [Keystone5000]
TP20  (no value)  [Keystone5000]
TP21  (no value)  [Keystone5000]
TP22  (no value)  [Keystone5000]
U7  TVS0500DRVR  [DRV0006A]
U8  TPS3840PL28DBVR  [DBV0005A_N]
U9  TVS0500DRVR  [DRV0006A]
U10  TPS3840PL28DBVR  [DBV0005A_N]
U11  TPS3840PL28DBVR  [DBV0005A_N]
U12  CPC1303GR  [IXYS_CPC1303GR]
U13  TVS1400DRVR  [DRV0006A]
U14  TVS0500DRVR  [DRV0006A]

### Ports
GFD_1, GFD_2, GFD_out, OPTO_out

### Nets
BIN_V_IN: J23.1 R13.1 TP22.1 U13.4(IN) U13.5(IN) U13.6(IN)
GND_BV: C23.2 C24.1 C25.2 D10.2(A) J23.2 R14.1 U11.3(GND) U12.2(K) U14.4(IN) U14.5(IN) U14.6(IN)
GND_GF: C17.2 C18.1 C19.2 C20.2 C21.1 C22.2 D5.2(A) D8.2(A) D12.2(K) D13.2(K) J20.1 R9.1 R10.1 U8.3(GND) U10.3(GND)
GND_OPT: J22.3 U12.3(E)
I_TD_in1: D2.2(A) D6.1(K) J18.1 U7.4(IN) U7.5(IN) U7.6(IN)
I_TD_in2: D3.2(A) D7.1(K) J18.2 U9.4(IN) U9.5(IN) U9.6(IN)
VCC_OPT: J22.1 R16.2
GFD_1: D1.2(A) R26.2 TP13.1 U8.1(~{RESET}) ; port GFD_1
GFD_2: D4.2(A) R27.2 TP15.1 U10.1(~{RESET}) ; port GFD_2
GFD_out: D1.1(K) D4.1(K) TP14.1 ; port GFD_out
OPTO_out: J22.2 R16.1 R17.2 TP21.1 ; port OPTO_out
NetC17_1: C17.1 J17.1
NetC18_2: C18.2 D5.1(K) R7.1 R9.2 TP16.1 U8.2(VDD)
NetC19_1: C19.1 J17.3
NetC20_1: C20.1 J19.1
NetC21_2: C21.2 D8.1(K) R8.1 R10.2 TP17.1 U10.2(VDD)
NetC22_1: C22.1 J19.3
NetC23_1: C23.1 J21.1
NetC24_2: C24.2 D10.1(K) R12.1 R14.2 TP20.1 U11.2(VDD)
NetC25_1: C25.1 J21.3
NetD2_1: D2.1(K) D3.1(K) J16.1
NetD6_2: D6.2(A) D7.2(A) J20.2
NetD9_1: D9.1(A) R17.1
NetD9_2: D9.2(K) U12.4(C)
NetD12_1: D12.1(A) R26.1
NetD13_1: D13.1(A) R27.1
NetJ16_2: J16.2 R7.2 R8.2
NetJ17_2: J17.2 U8.5(CT)
NetJ19_2: J19.2 U10.5(CT)
NetJ21_2: J21.2 U11.5(CT)
NetR11_1: R11.1 TP18.1 U11.1(~{RESET})
NetR11_2: R11.2 U12.1(A)
NetR12_2: R12.2 R13.2 TP19.1
NetU7_1: U7.1(GND) U7.2(GND) U7.3(GND) U7.7(PAD) U9.1(GND) U9.2(GND) U9.3(GND) U9.7(PAD)
NetU13_1: U13.1(GND) U13.2(GND) U13.3(GND) U13.7(PAD) U14.1(GND) U14.2(GND) U14.3(GND) U14.7(PAD)

Not connected (* = marked no-connect by the designer): U8 4(~{MR})*; U10 4(~{MR})*; U11 4(~{MR})*

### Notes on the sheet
- Ground fault detection
- Binary Voltage

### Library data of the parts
C17 C20 C23 = CMP-0009119-1: as C1 on sheet TIDA-010041-E1_Power sequencing, Reset, WDT
C18 C21 C24 = CMP-0007565-2: as C3 on sheet TIDA-010041-E1_Power sequencing, Reset, WDT
C19 C22 C25 = CMP-0007629-2: as C4 on sheet TIDA-010041-E1_Power sequencing, Reset, WDT
D1 D4 = CMP-0077033-2: Diode, Schottky, 20 V, 1 A, SOD-123F; Manufacturer: Nexperia; PartNumber: PMEG2010AEH,115; SizeArea_mm2: 5.6; Value2: 0.43V; AEC Category: Q101; SizeY_mm: 1.6; Vf_V: 430mV; Green_REACh: Incomplete; Value1: 1A; Value: 20V; SizeX_mm: 3.5; SizeAreaWB_mm2: 11.7; Green_Lifecycle: Not Set; TJmax_C: 150°C; SizeZ_mm: 1.1
D2 D3 D6 D7 = CMP-0029022-1: Diode, Superfast Rectifier, 100 V, 1 A, SMA; Manufacturer: Diodes Inc.; Io_A: 1A; Green_Lifecycle: Not Set; SizeAreaWB_mm2: 37.3428; Vr_V: 100V; Green_REACh: Incomplete; TJmax_C: 150°C; U/M: EA; Value: 100V; SizeZ_mm: 2.87; SizeX_mm: 5.59; SizeY_mm: 2.92; Vf_V: 9.2dV; Value2: 0.92V; SizeArea_mm2: 16.3228; AEC Category: Q101; RJC_CperW: 25
D5 D8 D10 = CMP-0005850-1: Diode, Zener, 3.6 V, 200 mW, SOD-323; Manufacturer: Diodes Inc.; Power_W: 200mW; SizeAreaWB_mm2: 8.695; Value1: 0.2W; RJA_CperW: 350; U/M: EA; SizeZ_mm: 1; SizeX_mm: 2.7; SizeY_mm: 1.35; SizeArea_mm2: 3.645; AEC Category: Q101
D9 D12 D13 = CMP-0002976-2: as D11 on sheet TIDA-010041-E1_Power sequencing, Reset, WDT
J16 J20 = CMP-0054566-1: as J2 on sheet TIDA-010041-E1_Power sequencing, Reset, WDT
J17 J19 J21 J22 = CMP-0054796-1: as J1 on sheet TIDA-010041-E1_Power sequencing, Reset, WDT
J18 J23 = CMP-0074910-1: as J4 on sheet TIDA-010041-E1_Power sequencing, Reset, WDT
R7 = CMP-0018892-2: RES, 160, 0.1%, 0.125 W, 0805; Manufacturer: Susumu Co Ltd; Power_W: 125mW; TempCo: 25 ppm/C; Value_Code: 160R; U/M: EA; Value: 160; EIA_Code: E192; SizeX_mm: 2; SizeY_mm: 1.25; SizeZ_mm: 1.45; Value2: 0.125W; SizeArea_mm2: 2.5; VDC_V: 100V; AEC Category: Q200
R8 = ERJ-6ENF49R9V: RES, 49.9, 1%, 0.125 W, 0805; Manufacturer: Panasonic; CompType: Resistor; Value: 49.9; Value_Code: 49R9; Tolerance_%: 1; Power_W: 0.125; Value2: 0.125W; VDC_V: 150; TempCo: 100 ppm/C; SizeArea_mm2: 2.5; SizeX_mm: 2; SizeY_mm: 1.25; SizeZ_mm: 1.45; EIA_Code: E96; U/M: EA; AEC Category: Q200; Green_Lifecycle: Active; Green_REACh: Passed
R9 = CRCW080540R2FKEA: RES, 40.2, 1%, 0.125 W, 0805; Manufacturer: Vishay-Dale; CompType: Resistor; Value: 40.2; Value_Code: 40R2; Tolerance_%: 1; Power_W: 0.125; Value2: 0.125W; VDC_V: 150; TempCo: 100 ppm/C; SizeArea_mm2: 2.5; SizeX_mm: 2; SizeY_mm: 1.25; SizeZ_mm: 1.45; EIA_Code: E96; U/M: EA; AEC Category: Q200; Green_Lifecycle: Active; Green_REACh: Passed
R10 = CMP-0018885-2: RES, 150, 0.1%, 0.125 W, 0805; Manufacturer: Susumu Co Ltd; Power_W: 125mW; TempCo: 25 ppm/C; Value_Code: 150R; U/M: EA; Value: 150; EIA_Code: E192; SizeX_mm: 2; SizeY_mm: 1.25; SizeZ_mm: 1.45; Value2: 0.125W; SizeArea_mm2: 2.5; VDC_V: 100V; AEC Category: Q200
R11 = CMP-0019144-2: RES, 1.50 k, 0.5%, 0.1 W, 0805; Manufacturer: Susumu Co Ltd; Power_W: 100mW; TempCo: 25 ppm/C; Value_Code: 1k50; U/M: EA; Value: 1.50k; EIA_Code: E192; Res_ohm: 1.5k; SizeX_mm: 2; SizeY_mm: 1.25; SizeZ_mm: 1.45; Value2: 0.1W; SizeArea_mm2: 2.5; VDC_V: 100V; AEC Category: Q200
R12 R14 = ERJ-6GEYJ204V: RES, 200 k, 5%, 0.125 W, 0805; Manufacturer: Panasonic; CompType: Resistor; Value: 200k; Res_ohm: 200000; Tolerance_%: 5; Power_W: 0.125; Value2: 0.125W; VDC_V: 150; TempCo: 200 ppm/C; SizeArea_mm2: 2.5; SizeX_mm: 2; SizeY_mm: 1.25; SizeZ_mm: 1.45; EIA_Code: E24; U/M: EA; AEC Category: Q200
R13 = CMP-0018855-2: RES, 1.00 k, 0.1%, 0.125 W, 0805; Manufacturer: Susumu Co Ltd; Power_W: 125mW; TempCo: 25 ppm/C; Value_Code: 1k00; U/M: EA; Value: 1.00k; EIA_Code: E192; Res_ohm: 1k; SizeX_mm: 2; SizeY_mm: 1.25; SizeZ_mm: 1.45; Value2: 0.125W; SizeArea_mm2: 2.5; VDC_V: 100V; AEC Category: Q200
R16 = ERJ-3EKF1000V: RES, 100, 1%, 0.1 W, AEC-Q200 Grade 0, 0603; Manufacturer: Panasonic; CompType: Resistor; Value: 100; Value_Code: 100R; Tolerance_%: 1; Power_W: 0.1; Value2: 0.1W; TempCo: 100 ppm/C; SizeArea_mm2: 1.28; SizeX_mm: 1.6; SizeY_mm: 0.8; EIA_Code: E96; U/M: EA; AEC Category: Q200; AEC Qualified: Y; AEC Grade: 0; Green_Lifecycle: Active; Green_REACh: Passed
R17 = ERJ-3GEY0R00V: RES, 0, 5%, 0.1 W, 0603; Manufacturer: Panasonic; CompType: Resistor; Value: 0; Value_Code: 0000; Tolerance_%: 5; Power_W: 0.1; Value2: 0.1W; VDC_V: 50; TempCo: 600 ppm/C; SizeArea_mm2: 1.28; SizeX_mm: 1.6; SizeY_mm: 0.8; SizeZ_mm: 1; EIA_Code: E24; U/M: EA; AEC Category: Q200; Green_Lifecycle: Active; Green_REACh: Passed
R26 R27 = CRCW06033K00JNEA: RES, 3.0 k, 5%, 0.1 W, 0603; Manufacturer: Vishay-Dale; CompType: Resistor; Value: 3.0k; Res_ohm: 3000; Value_Code: 3k00; Tolerance_%: 5; Power_W: 0.1; Value2: 0.1W; VDC_V: 75; TempCo: 200 ppm/C; SizeArea_mm2: 1.28; SizeX_mm: 1.6; SizeY_mm: 0.8; SizeZ_mm: 1; EIA_Code: E24; U/M: EA; AEC Category: Q200; Green_Lifecycle: Active; Green_REACh: Passed
TP13-TP20 TP22 = CMP-0055137-1: as TP1 on sheet TIDA-010041-E1_Power sequencing, Reset, WDT
TP21 = CMP-0055137-1: Test Point, Miniature, Red, TH; Manufacturer: Keystone; PartNumber: 5000; CNHeader: FALSE; Green_Lifecycle: Active; Green_REACh: Passed; ContactFinish: Silver; CT: TRUE
U7 U9 U14 = CMP-0077837-1: 5-V Precision Surge Protection Clamp, DRV0006A (WSON-6); Alternate Manufacturer: Texas Instruments; SizeAreaWB_mm2: 9.0; SizeZ_mm: 0.8; SizeX_mm: 2.0; SizeArea_mm2: 4.0; CompType: IC; AEC Qualified: N; AEC Category: Q200
U8 U10 U11 = CMP-0079923-1: as U1 on sheet TIDA-010041-E1_Power sequencing, Reset, WDT
U12 = CMP-0006170-3: Optocoupler, 5 kV, 200-2500% CTR, SMT; Manufacturer: IXYS; CTR (Max): 2500%; CTR (Min): 200%; Voltage_Isolation_Vrms: 5kV
U13 = CMP-0077836-1: 14-V Precision Surge Protection Clamp, DRV0006A (WSON-6); Alternate Manufacturer: Texas Instruments; SizeAreaWB_mm2: 9.0; SizeZ_mm: 0.8; SizeX_mm: 2.0; SizeArea_mm2: 4.0; CompType: IC; AEC Qualified: N; AEC Category: Q200

## Sheet TIDA-010041-E1_EVM_Hardware.SchDoc
size 431 x 279 mm; Date: Not shown in title block; ApprovedBy: Not shown in title block; CheckedBy: Not shown in title block; Author: Not shown in title block; CompanyName: Not shown in title block; Engineer: Not shown in title block; Organization: Not shown in title block; Address1: Not shown in title block; Address2: Not shown in title block; Address3: Not shown in title block; Address4: Not shown in title block; DocumentNumber: 1; Revision: Use project parameter SCH_Rev; SheetNumber: 5; SheetTotal: 5; PageSetup: Record=PageOptions¦CenterHorizontal=True¦CenterVertical=True¦PrintScale=1.00¦XCorrection=1.00¦YCorrection=1.00¦PrintKind=0¦BorderSize=5000000¦LeftOffset=0¦BottomOffset=0¦Orientation=2¦PaperLength=1000¦PaperWidth=1000¦Scale=100¦PaperSource=15¦PrintQuality=600¦MediaType=1¦DitherType=10¦PaperKind=Letter¦PrintScaleMode=1
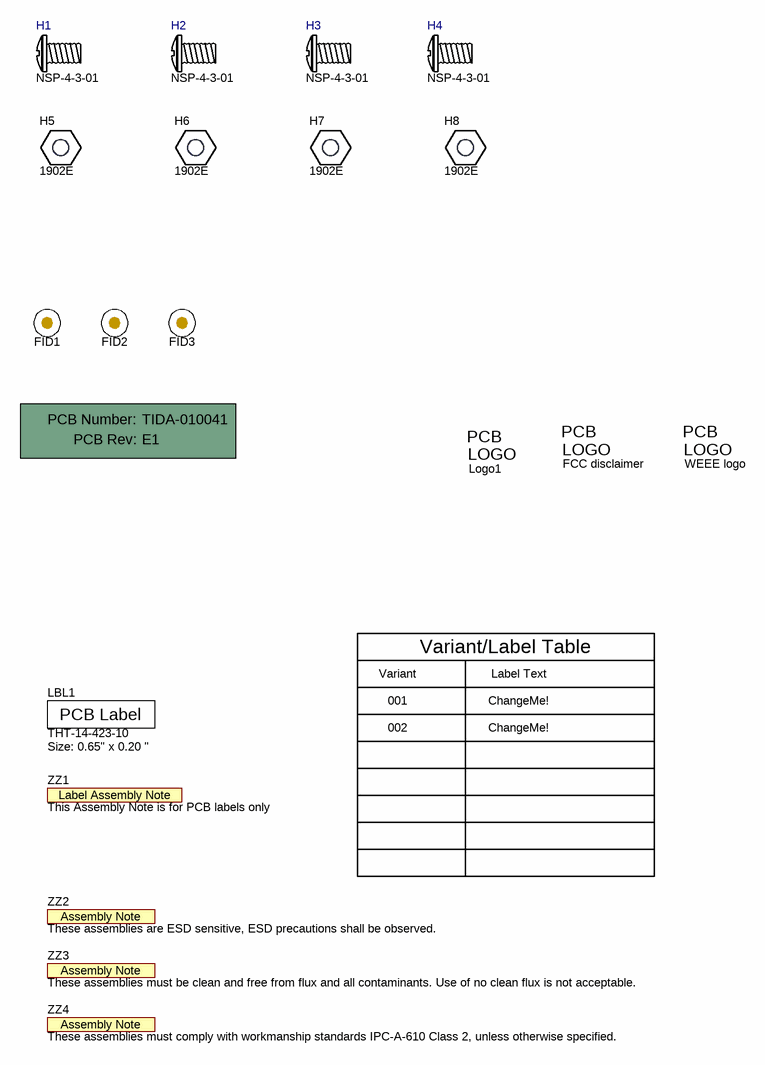
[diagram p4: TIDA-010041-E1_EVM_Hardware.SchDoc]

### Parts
!PCB  Printed Circuit Board  (value not drawn)  (mechanical)
FID1  Fiducial  [Fiducial10-20]  (value not drawn)
FID2  Fiducial  [Fiducial10-20]  (value not drawn)
FID3  Fiducial  [Fiducial10-20]  (value not drawn)
H1  NSP-4-3-01  [B_F_PMSSS4400025PH]
H2  NSP-4-3-01  [B_F_PMSSS4400025PH]
H3  NSP-4-3-01  [B_F_PMSSS4400025PH]
H4  NSP-4-3-01  [B_F_PMSSS4400025PH]
H5  1902E  [Keystone_1902E]
H6  1902E  [Keystone_1902E]
H7  1902E  [Keystone_1902E]
H8  1902E  [Keystone_1902E]
LBL1  THT-14-423-10  Note: Size: 0.65" x 0.20 "  [Label_650x200]
Logo1  ESD Susceptible  [ESD_Overlay_Medium]  (value not drawn)  (no BOM)
Logo3  FCC disclaimer  [FCC_disclaimer]  (no BOM)
Logo4  WEEE logo  [WEEE_Minimum]  (no BOM)
ZZ1  This Assembly Note is for PCB labels only  [AssemblyNoteLabel]  (no BOM)
ZZ2  These assemblies are ESD sensitive, ESD precautions shall be observed.  [AssemblyNote]  (no BOM)
ZZ3  These assemblies must be clean and free from flux and all contaminants. Use of no clean flux is not acceptable.  [AssemblyNote]  (no BOM)
ZZ4  These assemblies must comply with workmanship standards IPC-A-610 Class 2, unless otherwise specified.  [AssemblyNote]  (no BOM)

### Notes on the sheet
- Variant
- Variant/Label Table
- Label Text
- 001
- 002
- ChangeMe!

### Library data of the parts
!PCB = CMP-0003618-2: Manufacturer: Any; PartNumber: TIDA-010041
FID1-FID3 = CMP-0077181-1: Fiducial mark.  There is nothing to buy or mount.
H1-H4 = PMSSS 440 0025 PH: MACHINE SCREW PAN PHILLIPS 4-40; Manufacturer: Essentra Components; CompType: Standoff; SymbolCreator: a0412235
H5-H8 = 1902E: Standoff, Hex, 1"L #4-40 Nylon; Manufacturer: Keystone; CompType: Hardware; SymbolCreator: a0412235
LBL1 = CMP-0003625-1: Thermal Transfer Printable Labels, 0.650" W x 0.200" H - 10,000 per roll; Manufacturer: Brady; CompType: Label
Logo1 = ESD_Susceptible: ESD Susceptible Symbol; SymbolCreator: a0412235
Logo3 = CMP-0074847-1: FCC_disclaimer; Library Reference: Logo
Logo4 = CMP-0074769-1
ZZ1 = CMP-0003616-3
ZZ2 = CMP-0077236-1
ZZ3 = CMP-0077237-1
ZZ4 = CMP-0077238-1

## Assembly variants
001: not fitted C8 FID1 FID2 FID3 R22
